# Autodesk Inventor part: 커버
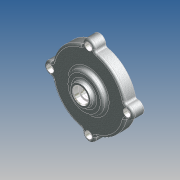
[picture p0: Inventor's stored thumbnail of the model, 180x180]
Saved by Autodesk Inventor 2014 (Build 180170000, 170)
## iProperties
Created: 2012-05
Part Number: 커버
Document SubType Name: 모델링
Designer: SeoGD™
Material: 알루미늄 6061
Mass: 72.5671 g
Surface Area: 278.607 cm^2
Volume: 72.5671 cm^3
Density: 1 g/cm^3
Appearance: 알루미늄 캐스트
변환 표준: STEP AP214IS
파일 이름: C:\Users\SeoGD\Desktop\?쒗뿕\而ㅻ쾭-1.stp
전처리기: Build: 253, Release: 2010 SP1 - Date: Wed 07/29/2009
전송 단위: 밀리미터
불확실성: 0.01
Author: SeoGD™
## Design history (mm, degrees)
sketch "스케치1"
  geometry: L1 (0, 0)-(0, 26); L2 (50, 0)-(50, 15); L3 (50, 15)-(25, 15); L4 (25, 15)-(25, 21); L5 (25, 21)-(15, 21); L6 (15, 21)-(13.66, 26); L7 (13.66, 26)-(10, 26); L8 (50, 0)-(45, 0); L9 (45, 0)-(45, 10); L10 (45, 10)-(14.5, 10); L11 (14.5, 10)-(13.266, 3); L12 (13.266, 3)-(11, 3); L13 (11, 3)-(11, 16); L14 (11, 16)-(7.5, 16); L15 (7.5, 16)-(7.5, 19); L16 (7.5, 19)-(10, 19); L17 (10, 19)-(10, 26)
  constraints: 34 end point, 10 parallel, 2 perpendicular, 2 point on line, 1 vertical
  dimensions: "d11" = 100 diameter of L2 L1; "d12" = 22 diameter of L13 L1; "d13" = 90 diameter of L9 L1; "d14" = 15 distance between parallel lines of L3 L8; "d15" = 10 distance between parallel lines of L8 L10; "d16" = 29 diameter of L10.end L1; "d17" = 100 deg angle of L11 L10; "d18" = 7 distance between parallel lines of L12 L10; "d19" = 13 distance between parallel lines of L14 L12; "d20" = 3 distance between parallel lines of L16 L14; "d21" = 15 diameter of L15 L1; "d22" = 20 diameter of L17 L1; "d23" = 30 diameter of L5.end L1; "d24" = 6 distance between parallel lines of L5 L3; "d25" = 50 diameter of L4 L1; "d26" = 105 deg angle of L5 L6; "d50" = 26 distance of L1.start L1.end
revolve "회전1" sketch "스케치1" stored, may be unused: angle "d27" = 90 deg
sketch "스케치2" dims "d29" = 104
  geometry: A1 r 8.5 centre (0, 52) between (8.074, 49.344) and (-8.074, 49.344); A2 r 50 centre (0, 0) between (-8.074, 49.344) and (8.074, 49.344) reference; 2 further points
  constraints: 4 point on circle, 2 vertical alignment, 1 centre point, 1 coincident, 2 other
  dimensions: "d28" = 17 diameter of A1
extrude "돌출1" join sketch "스케치2" stored distance "d30" = 10; taper "d31" = 0 deg
fillet "모깎기3" dims "d32" = 3
fillet "모깎기4" dims "d45" = 3, "d46" = 0.2
chamfer "모따기1" distance "d47" = 1; stored, may be unused: second distance "d48" = 2, angle "d49" = 45 deg
hole "구멍2" diameter "d38" = 5.5; stored, may be unused: countersink angle "d42" = 90 deg, drill point angle "d44" = 118 deg; dims "d36" = 10, "d37" = 10, "d39" = 6, "d40" = 9.5, "d41" = 5.4, "d43" = 8
node "솔리드1"
node "솔리드 본체"
node "곡면 본체"
pattern_circular "원형 패턴1" dims angle "d34" = 360 deg
pattern_circular "원형 패턴2" dims angle "d52" = 360 deg
node "솔리드2"
